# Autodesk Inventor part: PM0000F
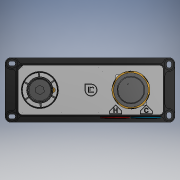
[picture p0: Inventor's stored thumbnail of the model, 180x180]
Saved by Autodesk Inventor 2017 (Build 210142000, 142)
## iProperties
Created: 2021-07
Part Number: PM0000F
Material: Generico
Document SubType Name: Modeling
Designer: CIANI
Density: 1 g/cm^3
Appearance: Default
Author: CIANI
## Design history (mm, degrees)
feature "Base2"
node "Solido1"
node "Solido3"
